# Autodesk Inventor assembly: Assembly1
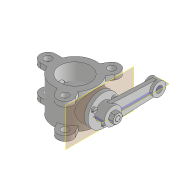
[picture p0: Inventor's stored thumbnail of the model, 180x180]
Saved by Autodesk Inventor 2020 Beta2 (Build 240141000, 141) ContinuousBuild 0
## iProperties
Created: 2019-03
Part Number: Assembly1
Document SubType Name: Assembly
Designer: LENOVO-CADCIM
Author: LENOVO-CADCIM
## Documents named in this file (10)
- D:\Autodesk Inventor_2020\c09\Butterfly Valve\Assembly1.iam
- D:\Autodesk Inventor_2020\c09\Butterfly Valve\Body.ipt
- D:\Autodesk Inventor_2020\c09\Butterfly Valve\Shaft.ipt
- D:\Autodesk Inventor_2020\c09\Butterfly Valve\Retainer.ipt
- D:\Autodesk Inventor_2020\c09\Butterfly Valve\Arm1.ipt
- D:\Autodesk Inventor_2020\c09\Butterfly Valve\Plate.ipt
- D:\Autodesk Inventor_2020\c09\Butterfly Valve\scew1.ipt
- D:\Autodesk Inventor_2020\c09\Butterfly Valve\Screw.ipt
- D:\Autodesk Inventor_2020\c09\Butterfly Valve\Parallel key.ipt
- D:\Autodesk Inventor_2020\c09\Butterfly Valve\Nut.ipt
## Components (12 placed, 9 different names)
1. Body:1 — Insert:1, Insert:2, Mate:1, Angle:2, Angle:3, Angle:4
2. Shaft:1 — Insert:1, Angle:2, Angle:3, Insert:3, Insert:4, Mate:3, Insert:11
3. Retainer:1 — Insert:2, Mate:1, Insert:7, Insert:8, Insert:9, Insert:10
4. Arm1:1 — Insert:10, Mate:2, Flush:1
5. Plate:1 — Insert:3, Insert:4, Insert:5, Insert:6
6. scew1:1 — Insert:5
7. scew1:2 — Insert:6
8. Screw:1 — Insert:7
9. Screw:2 — Insert:8
10. Screw:3 — Insert:9
11. Parallel key:1 — Mate:2, Mate:3, Flush:1
12. Nut:1 — Insert:11, Angle:4
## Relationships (18: Insert 11, Mate 3, Angle 3, Flush 1)
- Insert:1: Body:1 ↔ Shaft:1
- Insert:2: Body:1 ↔ Retainer:1
- Mate:1: Body:1 ↔ Retainer:1
- Angle:2: Body:1 ↔ Shaft:1
- Angle:3: Body:1 ↔ Shaft:1
- Insert:3: Shaft:1 ↔ Plate:1
- Insert:4: Shaft:1 ↔ Plate:1
- Insert:5: Plate:1 ↔ scew1:1
- Insert:6: Plate:1 ↔ scew1:2
- Insert:7: Retainer:1 ↔ Screw:1
- Insert:8: Retainer:1 ↔ Screw:2
- Insert:9: Retainer:1 ↔ Screw:3
- Insert:10: Retainer:1 ↔ Arm1:1
- Mate:2: Arm1:1 ↔ Parallel key:1
- Mate:3: Shaft:1 ↔ Parallel key:1
- Flush:1: Arm1:1 ↔ Parallel key:1
- Insert:11: Shaft:1 ↔ Nut:1
- Angle:4: Body:1 ↔ Nut:1
